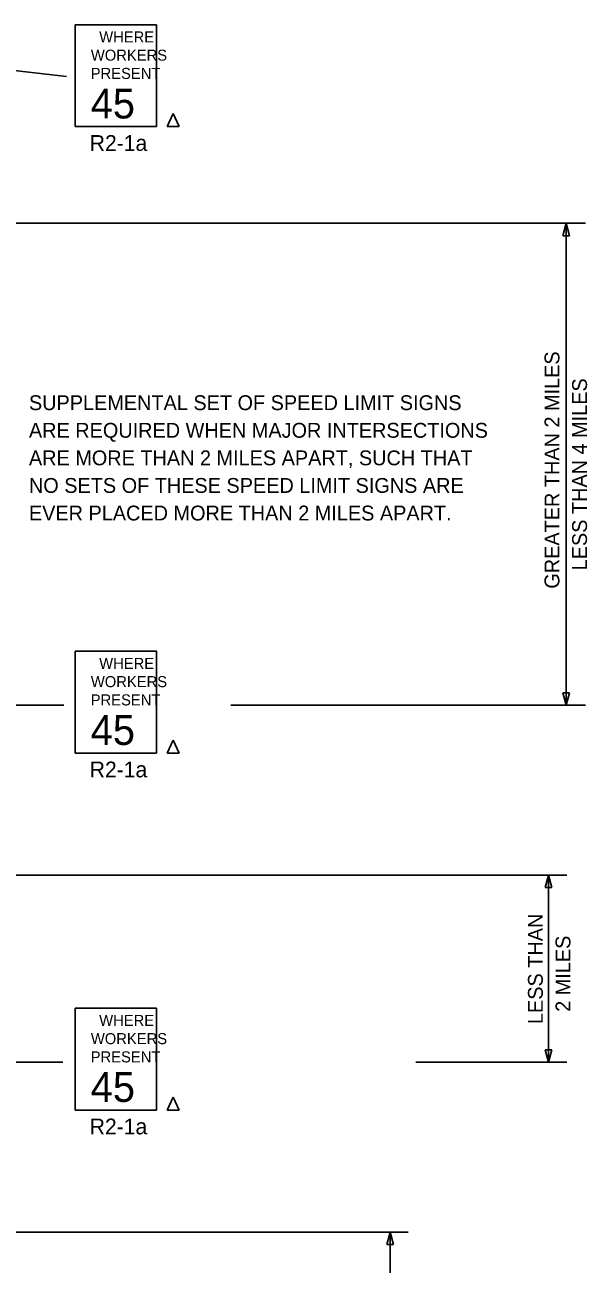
# Model space of a CAD drawing. Extents: x 16735 to 18480, y 5932 to 6927.
# Drawn here: x 17153 to 17418, y 6340 to 6924 of the extents above; entities that cross this region are included whole.
import ezdxf

# ---------------------------------------------------------------- set-up
doc = ezdxf.new("R2010")
doc.units = 0
doc.layers.add('TRAFFIC_SIGNS_PR', color=7, linetype='Continuous')
doc.layers.add('TYPICAL_TEXT_DIMEN_PR', color=7, linetype='Continuous')

msp = doc.modelspace()

# ---------------------------------------------------------------- linework, layer by layer
at = {"layer": 'TRAFFIC_SIGNS_PR'}
for p, q in [((17176.77, 6923.94), (17215.17, 6923.94)), ((17176.77, 6875.94), (17176.77, 6923.94)), ((17215.17, 6875.94), (17215.17, 6923.94)), ((17176.77, 6875.94), (17215.17, 6875.94)), ((17176.77, 6628.69), (17215.17, 6628.69)), ((17176.77, 6580.69), (17176.77, 6628.69)), ((17215.17, 6580.69), (17215.17, 6628.69)), ((17176.77, 6580.69), (17215.17, 6580.69)), ((17176.77, 6460.43), (17215.17, 6460.43)), ((17176.77, 6412.43), (17176.77, 6460.43)), ((17215.17, 6412.43), (17215.17, 6460.43)), ((17176.77, 6412.43), (17215.17, 6412.43))]:
    msp.add_line(p, q, dxfattribs=at)
for points in [[(17222.99, 6882.12), (17220.19, 6875.94)], [(17220.19, 6875.94), (17222.99, 6882.12)], [(17225.78, 6875.94), (17222.99, 6882.12)], [(17222.99, 6882.12), (17225.78, 6875.94)], [(17220.19, 6875.94), (17225.78, 6875.94)], [(17225.78, 6875.94), (17220.19, 6875.94)], [(17222.99, 6586.86), (17220.19, 6580.69)], [(17220.19, 6580.69), (17222.99, 6586.86)], [(17225.78, 6580.69), (17222.99, 6586.86)], [(17222.99, 6586.86), (17225.78, 6580.69)], [(17220.19, 6580.69), (17225.78, 6580.69)], [(17225.78, 6580.69), (17220.19, 6580.69)], [(17222.99, 6418.6), (17220.19, 6412.43)], [(17220.19, 6412.43), (17222.99, 6418.6)], [(17225.78, 6412.43), (17222.99, 6418.6)], [(17222.99, 6418.6), (17225.78, 6412.43)], [(17220.19, 6412.43), (17225.78, 6412.43)], [(17225.78, 6412.43), (17220.19, 6412.43)]]:
    msp.add_lwpolyline(points, dxfattribs=at)
at = {"layer": 'TYPICAL_TEXT_DIMEN_PR'}
for p, q in [((17079.34, 6910.39), (17172.69, 6899.57)), ((17417.27, 6830.39), (16992.61, 6830.39)), ((17406.59, 6824.53), (17408.16, 6830.39)), ((17408.16, 6830.39), (17409.73, 6824.53)), ((17408.16, 6830.39), (17408.16, 6603.21)), ((17408.16, 6824.53), (17406.59, 6824.53)), ((17409.73, 6824.53), (17408.16, 6824.53)), ((17408.16, 6603.21), (17406.59, 6609.07)), ((17406.59, 6609.07), (17408.16, 6609.07)), ((17408.16, 6609.07), (17409.73, 6609.07)), ((17409.73, 6609.07), (17408.16, 6603.21)), ((17171.43, 6603.21), (16993, 6603.21)), ((17417.27, 6603.21), (17250.08, 6603.21)), ((17408.16, 6603.21), (17408.16, 6603.21)), ((17408.46, 6523.21), (16992.61, 6523.21)), ((17398.35, 6517.35), (17399.92, 6523.21)), ((17399.92, 6523.21), (17399.92, 6434.95)), ((17399.92, 6523.21), (17401.49, 6517.35)), ((17399.92, 6517.35), (17398.35, 6517.35)), ((17401.49, 6517.35), (17399.92, 6517.35)), ((17399.92, 6434.95), (17398.35, 6440.81)), ((17398.35, 6440.81), (17399.92, 6440.81)), ((17399.92, 6440.81), (17401.49, 6440.81)), ((17401.49, 6440.81), (17399.92, 6434.95)), ((17170.95, 6434.95), (16991.66, 6434.95)), ((17408.46, 6434.95), (17337.3, 6434.95)), ((17399.92, 6434.95), (17399.92, 6434.95)), ((17333.74, 6354.95), (16992.61, 6354.95)), ((17323.69, 6349.09), (17325.26, 6354.95)), ((17325.26, 6354.95), (17325.26, 6184.31)), ((17325.26, 6354.95), (17326.83, 6349.09)), ((17325.26, 6349.09), (17323.69, 6349.09)), ((17326.83, 6349.09), (17325.26, 6349.09))]:
    msp.add_line(p, q, dxfattribs=at)

# ---------------------------------------------------------------- texts
at = {"layer": 'TRAFFIC_SIGNS_PR'}
for s, height, p in [('WHERE', 5.2, (17188.09, 6915.63)), ('WORKERS', 5.2, (17184.16, 6907.03)), ('PRESENT', 5.2, (17184.09, 6898.43)), ('45', 14.031, (17184.08, 6879.8)), ('R2-1a', 7.44, (17183.63, 6864.5)), ('SUPPLEMENTAL SET OF SPEED LIMIT SIGNS', 7, (17154.97, 6742.33)), ('ARE REQUIRED WHEN MAJOR INTERSECTIONS', 7, (17154.97, 6729.33)), ('ARE MORE THAN 2 MILES APART, SUCH THAT', 7, (17154.97, 6716.33)), ('NO SETS OF THESE SPEED LIMIT SIGNS ARE', 7, (17154.97, 6703.33)), ('EVER PLACED MORE THAN 2 MILES APART.', 7, (17154.97, 6690.33)), ('WHERE', 5.2, (17188.09, 6620.37)), ('WORKERS', 5.2, (17184.16, 6611.77)), ('PRESENT', 5.2, (17184.09, 6603.17)), ('45', 14.031, (17184.08, 6584.54)), ('R2-1a', 7.44, (17183.63, 6569.25)), ('WHERE', 5.2, (17188.09, 6452.12)), ('WORKERS', 5.2, (17184.16, 6443.52)), ('PRESENT', 5.2, (17184.09, 6434.92)), ('45', 14.031, (17184.08, 6416.29)), ('R2-1a', 7.44, (17183.63, 6400.99))]:
    msp.add_text(s, height=height, dxfattribs=at).set_placement(p)
at = {"layer": 'TYPICAL_TEXT_DIMEN_PR'}
for s, p in [('GREATER THAN 2 MILES', (17404.99, 6658.19)), ('LESS THAN 4 MILES', (17417.99, 6666.82)), ('LESS THAN', (17397.17, 6452.99)), ('2 MILES', (17410.17, 6458.75))]:
    msp.add_text(s, height=7, rotation=90, dxfattribs=at).set_placement(p)

doc.saveas('drawing.dxf')
